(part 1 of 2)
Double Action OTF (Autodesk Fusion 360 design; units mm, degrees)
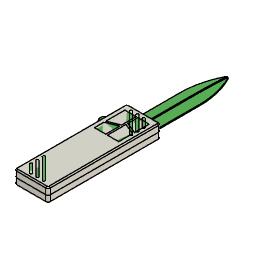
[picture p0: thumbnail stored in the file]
parameter "d3" = 3
parameter "d7" = 6
sketch "Sketch1" plane through (0, 0, 0) normal (0, 0, 1) x axis (1, 0, 0)
  line L1 (28, 2) -> (2, 2)
  line L2 (6, 96) -> (6, 100)
  line L3 (30, 0) -> (0, 0)
  line L4 (30, 100) -> (30, 0)
  line L5 (2, 98) -> (2, 2)
  line L6 (24, 96) -> (24, 100)
  line L7 (0, 100) -> (30, 100)
  line L8 (0, 0) -> (0, 100)
  line L9 (28, 98) -> (2, 98)
  line L10 (28, 2) -> (28, 98)
  line L11 (26, 4) -> (4, 4)
  line L12 (0.8, 36.7425) -> (0.8, 21)
  line L13 (24, 96) -> (26, 96)
  line L14 (4, 96) -> (6, 96)
  line L15 (5.1055, 19.9338) -> (0.9152, 44.9179)
  line L16 (4, 37.9285) -> (3, 37.9285)
  line L17 (4, 17.8) -> (0.8, 21)
  line L18 (4, 85) -> (0, 85)
  line L19 (4, 65) -> (0, 65)
  line L20 (29.2, 80) -> (26, 83.2)
  line L21 (29.2, 63.2575) -> (29.2, 80)
  line L22 (26, 62.0715) -> (26, 4)
  line L23 (26, 96) -> (26, 83.2)
  line L24 (26, 62.0715) -> (27, 62.0715)
  line L25 (28.014, 62.0715) -> (29.2, 63.2575)
  line L26 (24.8945, 80.0662) -> (29.0848, 55.0821)
  line L27 (24.1055, 79.9338) -> (28.1635, 55.7387)
  line L28 (4, 37.9285) -> (4, 96)
  line L29 (4, 4) -> (4, 17.8)
  line L30 (24, 96) -> (6, 96)
  line L31 (28.6, 44) -> (26, 44)
  line L32 (28.6, 4) -> (28.6, 44)
  line L33 (26, 4) -> (28.6, 4)
  line L34 (2.4, 54) -> (2.4, 65)
  line L35 (2.4, 96) -> (2.4, 85)
  line L36 (4, 96) -> (2.4, 96)
  line L37 (4, 54) -> (2.4, 54)
  line L38 (1.4, 4) -> (1.4, 20.4)
  line L39 (4, 4) -> (1.4, 4)
  line L40 (28.6, 96) -> (26, 96)
  line L41 (28.6, 80.6) -> (28.6, 96)
  line L42 (3, 37.9285) -> (1.9516, 44.1792)
  line L43 (1.986, 37.9285) -> (0.8, 45)
  line L44 (0.8, 36.7425) -> (1.986, 37.9285)
  line L45 (27, 62.0715) -> (28.0484, 55.8208)
  line L46 (28.014, 62.0715) -> (29.2, 55)
  line L47 (3.2, 44.3886) -> (1.9516, 44.1792)
  line L48 (3.0346, 45.3748) -> (3.2, 44.3886)
  line L49 (0.8, 45) -> (3.0346, 45.3748)
  line L50 (3.0848, 44.4706) -> (1.8365, 44.2613)
  line L51 (2.9525, 45.2596) -> (3.0848, 44.4706)
  line L52 (0.9152, 44.9179) -> (2.9525, 45.2596)
  line L53 (5.8945, 20.0662) -> (1.8365, 44.2613)
  line L54 (26.8, 55.6114) -> (28.0484, 55.8208)
  line L55 (26.9654, 54.6252) -> (26.8, 55.6114)
  line L56 (26.9654, 54.6252) -> (29.2, 55)
  line L57 (26.9152, 55.5294) -> (28.1635, 55.7387)
  line L58 (27.0475, 54.7404) -> (26.9152, 55.5294)
  line L59 (29.0848, 55.0821) -> (27.0475, 54.7404)
  line L60 (6, 4) -> (6, 96)
  line L61 (24, 4) -> (24, 96)
  line L62 (14, 4) -> (14, 96)
  line L63 (16, 4) -> (16, 96)
  circle C1 centre (2, 50) radius 1
  circle C2 centre (28, 98) radius 1
  circle C3 centre (2, 98) radius 1
  circle C4 centre (2, 2) radius 1
  circle C5 centre (28, 50) radius 1
  circle C6 centre (28, 2) radius 1
  arc A1 centre (5.5, 20) radius 0.4 clockwise from (5.8945, 20.0662) to (5.1055, 19.9338)
  arc A2 centre (24.5, 80) radius 0.4 clockwise from (24.1055, 79.9338) to (24.8945, 80.0662)
  point P6 (0, 0)
  point P15 (0, 0)
  point P14 (6, 100)
  point P12 (6, 96)
  point P3 (24, 100)
  point P17 (2, 98)
  point P21 (2, 98)
  point P10 (28, 2)
  point P23 (28, 2)
  point P11 (2, 2)
  point P22 (2, 2)
  point P9 (2, 50)
  point P24 (28, 50)
  point P25 (2, 98)
  point P13 (28, 98)
  point P20 (28, 98)
  point P1 (0, 0)
  point P29 (5.8523, 15.481)
  point P35 (4, 17.8)
  point P36 (0, 85)
  point P37 (4, 85)
  point P38 (0, 65)
  point P39 (4, 65)
  point P40 (26, 83.2)
  point P51 (26, 44)
  point P54 (2.4, 65)
  point P56 (2.4, 85)
  point P58 (4, 54)
  point P59 (1.4, 20.4)
  point P62 (28.6, 80.6)
  point P32 (5.8945, 20.0662)
  point P34 (5.8945, 20.0662)
  point P64 (1.986, 37.9285)
  point P42 (29.2, 63.2575)
  point P67 (29.2, 63.2575)
  point P45 (28.014, 62.0715)
  point P48 (24.8945, 80.0662)
  point P50 (24.8945, 80.0662)
  point P80 (6, 96)
  point P81 (6, 4)
  point P82 (24, 96)
  point P83 (24, 4)
  point P84 (14, 96)
  point P85 (14, 4)
  point P86 (16, 96)
  point P87 (16, 4)
  point P7 (30, 0)
  point P4 (0, 100)
  point P33 (5.5, 20)
  point P26 (0.8, 21)
  point P41 (29.2, 80)
  point P49 (24.5, 80)
  point P55 (2.4, 54)
  point P27 (4, 37.9285)
  point P28 (3, 37.9285)
  point P43 (26, 62.0715)
  point P44 (27, 62.0715)
  point P63 (0.8, 45)
  point P69 (3.2, 44.3886)
  point P66 (29.2, 55)
  point P75 (26.8, 55.6114)
  horizontal L3
  vertical L4
  horizontal L7
  vertical L8
  coincident P6 P15
  perpendicular L7 L28
  perpendicular L11 L28
  perpendicular L7 L22
  horizontal L13
  coincident P14 L7
  coincident P12 L13
  perpendicular L2 L13
  coincident P3 L7
  perpendicular L6 L13
  coincident P17 P21
  perpendicular L1 L4
  perpendicular L5 L7
  perpendicular L4 L9
  perpendicular L3 L10
  coincident P10 P23
  coincident P11 P22
  midpoint P9 L5
  midpoint P24 L10
  coincident P17 P25
  coincident P13 P20
  coincident P1 P6
  collinear L13 L14
  coincident P29 L15
  tangent L15 A1
  coincident P35 L28
  coincident L8 P36
  coincident P37 L28
  perpendicular L18 L28
  coincident L8 P38
  coincident P39 L28
  perpendicular L19 L28
  coincident P40 L22
  parallel L10 L21
  collinear L22 L23
  horizontal L24
  tangent L27 A2
  collinear L28 L29
  coincident L22 P51
  perpendicular L10 L31
  perpendicular L31 L32
  perpendicular L32 L33
  coincident L19 P54
  perpendicular L19 L34
  coincident L18 P56
  perpendicular L18 L35
  perpendicular L28 L36
  coincident L28 P58
  perpendicular L28 L37
  coincident L17 P59
  vertical L38
  perpendicular L38 L39
  perpendicular L23 L40
  coincident L20 P62
  perpendicular L40 L41
  coincident P32 P34
  horizontal L16
  coincident L16 P64
  coincident P42 P67
  coincident L24 P45
  coincident P48 P50
  tangent L26 A2
  parallel L15 L43
  perpendicular L42 L47
  perpendicular L43 L49
  perpendicular L50 L51
  parallel L49 L52
  parallel L48 L51
  parallel L47 L50
  parallel L15 L53
  tangent A1 L53
  parallel L27 L45
  perpendicular L45 L54
  perpendicular L54 L55
  perpendicular L27 L57
  perpendicular L57 L58
  perpendicular L46 L56
  parallel L56 L59
  coincident L30 P80
  coincident L11 P81
  perpendicular L11 L60
  coincident L30 P82
  coincident L11 P83
  perpendicular L11 L61
  coincident L30 P84
  coincident L11 P85
  perpendicular L11 L62
  coincident L30 P86
  coincident L11 P87
  perpendicular L11 L63
  dimension "d33" distance P6 P7 = 30
  dimension "d34" distance P4 P6 = 100
  dimension "d35" distance L4 L22 = 4
  dimension "d36" distance L3 L11 = 4
  dimension "d37" distance L7 L13 = 4
  dimension "d38" distance L2 L8 = 6
  dimension "d39" distance L4 L6 = 6 (= "d7")
  dimension "d40" distance L2 L6 = 18
  dimension "d41" distance L8 L28 = 4
  dimension "d42" diameter C2 = 2
  dimension "d43" diameter C1 = 2
  dimension "d44" diameter C5 = 2
  dimension "d45" diameter C4 = 2
  dimension "d46" diameter C6 = 2
  dimension "d47" distance L1 L3 = 2
  dimension "d48" distance L5 L8 = 2
  dimension "d49" diameter C3 = 2
  dimension "d50" distance L7 L9 = 2
  dimension "d51" distance L4 L10 = 2
  dimension "d64" distance L8 L12 = 0.8
  dimension "d87" distance L3 P33 = 20
  dimension "d89" angle L12 L17 = 135
  dimension "d90" distance L3 P26 = 21
  dimension "d95" distance L18 L19 = 20
  dimension "d96" distance L7 L18 = 15
  dimension "d100" angle L20 L21 = 135
  dimension "d101" distance L4 L21 = 0.8
  dimension "d102" distance L7 P41 = 20
  dimension "d105" angle L21 L25 = 135
  dimension "d115" distance L26 L27 = 0.8
  dimension "d118" distance L7 P49 = 20
  dimension "d204" distance L22 L32 = 2.6
  dimension "d205" distance L4 L32 = 1.4
  dimension "d206" distance L31 L33 = 40
  dimension "d225" distance P54 P55 = 11
  dimension "d226" distance L28 L35 = 1.6
  dimension "d227" distance L28 L34 = 1.6
  dimension "d282" distance L29 L38 = 2.6
  dimension "d283" distance L23 L41 = 2.6
  dimension "d311" distance L8 P33 = 5.5
  dimension "d328" distance L15 P64 = 0.1
  dimension "d329" distance P27 P28 = 1
  dimension "d330" angle L12 L44 = 135
  dimension "d331" distance P43 P44 = 1
  dimension "d335" distance P44 L27 = 0.1
  dimension "d338" distance L8 P63 = 0.8
  dimension "d340" distance L3 P63 = 45
  dimension "d341" distance L28 P69 = 0.8
  dimension "d343" distance L49 L52 = 0.1
  dimension "d344" distance L48 L51 = 0.1
  dimension "d345" distance L47 L50 = 0.1
  dimension "d346" distance L50 L52 = 0.8
  dimension "d347" distance L42 L53 = 0.1
  dimension "d348" distance L15 L53 = 0.8
  dimension "d350" distance L4 P66 = 0.8
  dimension "d351" distance L7 P66 = 45
  dimension "d352" distance L22 P75 = 0.8
  dimension "d353" distance L56 L59 = 0.1
  dimension "d354" distance L55 L58 = 0.1
  dimension "d355" distance L54 L57 = 0.1
  dimension "d356" distance L57 L59 = 0.8
  dimension "d362" distance L28 L60 = 2
  dimension "d363" distance L22 L61 = 2
  dimension "d364" distance L61 L63 = 8
  dimension "d365" distance L60 L62 = 8
  dimension "d366" distance L62 L63 = 2
  dimension "d376" distance L4 P49 = 5.5
sketch "Sketch1" plane through (0, 0, 0) normal (0, 0, 1) x axis (1, 0, 0)
  line L1 (26, 4) -> (4, 4)
  line L2 (6, 96) -> (6, 100)
  line L3 (0, 100) -> (30, 100)
  line L4 (24, 96) -> (24, 100)
  line L5 (25.85, 4.15) -> (6.15, 4.15)
  line L6 (12.15, 6.65) -> (12.15, 16.65)
  line L7 (17.85, 6.65) -> (17.85, 16.65)
  line L8 (15, 99.15) -> (15, 4.15)
  line L9 (6, 19.15) -> (6, 96)
  line L10 (24, 19.15) -> (24, 96)
  line L11 (6.15, 64.15) -> (6.15, 19.15)
  line L12 (23.85, 64.15) -> (23.85, 19.15)
  line L13 (24, 96) -> (26, 96)
  line L14 (16.85, 5.65) -> (13.15, 5.65)
  line L15 (16.85, 17.65) -> (13.15, 17.65)
  line L16 (26, 62.0715) -> (26, 4)
  line L17 (23.85, 19.15) -> (24.85, 19.15)
  line L18 (4.15, 19.15) -> (6.15, 19.15)
  line L19 (4, 37.9285) -> (4, 96)
  line L20 (4, 4) -> (4, 17.8)
  line L21 (23.85, 19.15) -> (6.15, 19.15)
  line L22 (16.85, 4.65) -> (13.15, 4.65)
  line L23 (16.85, 18.65) -> (13.15, 18.65)
  line L24 (17.85, 4.9179) -> (17.85, 6.65)
  line L25 (12.15, 4.9179) -> (12.15, 6.65)
  line L26 (12.15, 18.3821) -> (12.15, 16.65)
  line L27 (17.85, 18.3821) -> (17.85, 16.65)
  line L28 (5.8821, 14.15) -> (4.4179, 16.6859)
  line L29 (4.15, 17.6859) -> (4.15, 19.15)
  line L30 (25.5821, 6.6141) -> (24.1179, 9.15)
  line L31 (25.85, 5.6141) -> (25.85, 4.15)
  line L32 (6.15, 4.15) -> (6.15, 13.15)
  line L33 (23.85, 10.901) -> (23.85, 10.15)
  line L34 (24.85, 19.15) -> (23.8809, 11.3971)
  arc A1 centre (79.784, 64.15) radius 73.634 clockwise from (6.15, 64.15) to (15, 99.15)
  arc A2 centre (-49.784, 64.15) radius 73.634 clockwise from (15, 99.15) to (23.85, 64.15)
  arc A3 centre (13.15, 16.65) radius 1 clockwise from (12.15, 16.65) to (13.15, 17.65)
  arc A4 centre (16.85, 16.65) radius 1 clockwise from (16.85, 17.65) to (17.85, 16.65)
  arc A5 centre (16.85, 6.65) radius 1 clockwise from (17.85, 6.65) to (16.85, 5.65)
  arc A6 centre (13.15, 6.65) radius 1 clockwise from (13.15, 5.65) to (12.15, 6.65)
  arc A7 centre (13.15, 6.65) radius 2 clockwise from (13.15, 4.65) to (12.15, 4.9179)
  arc A8 centre (16.85, 6.65) radius 2 clockwise from (17.85, 4.9179) to (16.85, 4.65)
  arc A9 centre (16.85, 16.65) radius 2 clockwise from (16.85, 18.65) to (17.85, 18.3821)
  arc A10 centre (13.15, 16.65) radius 2 clockwise from (12.15, 18.3821) to (13.15, 18.65)
  arc A11 centre (6.15, 17.6859) radius 2 clockwise from (4.4179, 16.6859) to (4.15, 17.6859)
  arc A12 centre (4.15, 13.15) radius 2 clockwise from (5.8821, 14.15) to (6.15, 13.15)
  arc A13 centre (25.85, 10.15) radius 2 clockwise from (24.1179, 9.15) to (23.85, 10.15)
  arc A14 centre (23.85, 5.6141) radius 2 clockwise from (25.5821, 6.6141) to (25.85, 5.6141)
  arc A15 centre (27.85, 10.901) radius 4 clockwise from (23.85, 10.901) to (23.8809, 11.3971)
  point P6 (6, 96)
  point P15 (6, 96)
  point P16 (6, 19.15)
  point P10 (24, 96)
  point P17 (24, 96)
  point P18 (24, 19.15)
  point P19 (6.15, 19.15)
  point P54 (4.15, 6.15)
  point P53 (4.15, 17.15)
  point P61 (25.85, 17.15)
  point P62 (25.85, 6.15)
  point P13 (15, 4.15)
  point P71 (23.85, 11.15)
  point P20 (6.15, 64.15)
  point P14 (15, 99.15)
  point P12 (4.15, 19.15)
  point P11 (25.85, 4.15)
  point P70 (24.85, 19.15)
  point P63 (23.85, 10.15)
  horizontal L5
  vertical L31
  horizontal L17
  vertical L29
  perpendicular L5 L6
  perpendicular L1 L7
  perpendicular L3 L8
  coincident P6 P15
  coincident P16 L17
  perpendicular L9 L17
  coincident P10 P17
  coincident P18 L17
  perpendicular L10 L17
  coincident P19 L17
  perpendicular L11 L17
  perpendicular L12 L17
  equal L11 L12
  tangent L11 A1
  tangent L12 A2
  perpendicular L7 L14
  perpendicular L7 L15
  tangent L15 A3
  tangent L6 A3
  tangent L15 A4
  tangent L7 A4
  equal A3 A4
  tangent L14 A5
  tangent L7 A5
  equal A3 A5
  tangent L14 A6
  tangent L6 A6
  equal A3 A6
  collinear L17 L18
  tangent A5 L24
  tangent A6 L25
  concentric A6 A7
  concentric A5 A8
  tangent A7 L22
  tangent L22 A8
  tangent A3 L26
  tangent A4 L27
  concentric A4 A9
  concentric A3 A10
  tangent A9 L23
  tangent L23 A10
  coincident P54 L29
  coincident P53 L28
  coincident P53 L29
  tangent L28 A11
  tangent L29 A11
  tangent L28 A12
  equal A11 A12
  coincident P61 L31
  tangent L30 A13
  coincident P62 L30
  coincident P62 L31
  tangent L30 A14
  tangent L31 A14
  tangent A12 L32
  coincident L5 P13
  vertical L33
  tangent A13 L33
  coincident P71 L33
  coincident P71 L34
  tangent L33 A15
  tangent L34 A15
  collinear L12 L33
  dimension "d54" distance L1 L5 = 0.15
  dimension "d56" distance L6 L7 = 5.7
  dimension "d57" distance L6 L29 = 8
  dimension "d58" distance L7 L31 = 8
  dimension "d59" distance P19 P20 = 45
  dimension "d60" distance L9 L11 = 0.15
  dimension "d61" distance L10 L12 = 0.15
  dimension "d91" distance L14 L15 = 12
  dimension "d92" distance L5 L14 = 1.5
  dimension "d93" distance L15 L17 = 1.5
  dimension "d94" radius A3 = 1
  dimension "d119" distance L16 L31 = 0.15
  dimension "d129" distance P13 P14 = 95
  dimension "d139" distance L20 L29 = 0.15
  dimension "d313" distance P12 P53 = 2
  dimension "d316" angle L28 L29 = 30
  dimension "d318" radius A11 = 2
  dimension "d319" distance P11 P62 = 2
  dimension "d322" angle L30 L31 = 30
  dimension "d370" distance L29 L32 = 2
  dimension "d371" distance L5 L21 = 15
  dimension "d372" distance L12 P70 = 1
  dimension "d373" distance P63 P71 = 1
  dimension "d374" radius A15 = 4
  dimension "d375" radius A13 = 2
sketch "Sketch1" plane through (0, 0, 0) normal (0, 0, 1) x axis (1, 0, 0)
  line L1 (4, 85) -> (0, 85)
  line L2 (4, 96) -> (6, 96)
  line L3 (24, 96) -> (26, 96)
  line L4 (26, 96) -> (26, 83.2)
  line L5 (26, 62.0715) -> (26, 4)
  line L6 (4, 65) -> (0, 65)
  line L7 (0, 0) -> (0, 100)
  line L8 (26, 4) -> (4, 4)
  line L9 (4.2, 75.2) -> (0.1142, 75.2)
  line L10 (-0.3, 65.2) -> (-0.3, 75.2)
  line L11 (4.2, 65.2) -> (0.1142, 65.2)
  line L12 (4.2, 86.2) -> (4.2, 75.2)
  line L13 (25.8, 86.2) -> (4.2, 86.2)
  line L14 (-5.3, 70.2) -> (-0.3, 70.2)
  line L15 (-2.4716, 67.3716) -> (-0.5929, 65.4929)
  line L16 (-2.4716, 73.0284) -> (-0.5929, 74.9071)
  line L17 (7.2, 29.2665) -> (7.2, 17.2665)
  line L18 (4.2, 37.5089) -> (4.2, 65.2)
  line L19 (4, 37.9285) -> (4, 96)
  line L20 (4, 4) -> (4, 17.8)
  line L21 (12.15, 6.65) -> (12.15, 16.65)
  line L22 (17.85, 6.65) -> (17.85, 16.65)
  line L23 (10.8, 5.65) -> (12, 5.65)
  line L24 (10.8, 84.7) -> (10.8, 5.65)
  line L25 (12, 84.7) -> (10.8, 84.7)
  line L26 (12, 5.65) -> (12, 84.7)
  line L27 (25.85, 4.15) -> (6.15, 4.15)
  line L28 (18, 84.7) -> (18, 5.65)
  line L29 (19.2, 84.7) -> (18, 84.7)
  line L30 (19.2, 5.65) -> (19.2, 84.7)
  line L31 (18, 5.65) -> (19.2, 5.65)
  line L32 (22.85, 61.1908) -> (22.85, 73.1908)
  line L33 (25.85, 34.2) -> (25.85, 52.9483)
  line L34 (21.65, 60.9792) -> (21.65, 73.4568)
  line L35 (8.4, 29.4781) -> (8.4, 17.0004)
  line L36 (5.4, 86.2) -> (5.4, 65.2)
  line L37 (4.2, 75.2) -> (4.2, 65.2)
  line L38 (26, 4) -> (28.6, 4)
  line L39 (28.6, 4) -> (28.6, 44)
  line L40 (28.6, 44) -> (26, 44)
  line L41 (26.45, 4.15) -> (25.85, 4.15)
  line L42 (28.45, 32.2) -> (28.45, 6.15)
  line L43 (25.85, 34.2) -> (26.45, 34.2)
  line L44 (2.6, 86.2) -> (2.6, 75.2)
  line L45 (4.2, 86.2) -> (2.6, 86.2)
  line L46 (2.6, 54.4) -> (2.6, 65.2)
  line L47 (4.2, 54.4) -> (2.6, 54.4)
  line L48 (1.4, 4) -> (1.4, 20.4)
  line L49 (4, 4) -> (1.4, 4)
  line L50 (28.6, 96) -> (26, 96)
  line L51 (28.6, 80.6) -> (28.6, 96)
  line L52 (28.45, 86.2) -> (25.8, 86.2)
  line L53 (28.45, 85.2) -> (28.45, 86.2)
  line L54 (22.85, 73.1908) -> (28.45, 85.2)
  line L55 (27.5923, 86.2) -> (21.65, 73.4568)
  line L56 (1.55, 4.15) -> (6.15, 4.15)
  line L57 (1.55, 5.15) -> (1.55, 4.15)
  line L58 (1.55, 5.15) -> (7.2, 17.2665)
  line L59 (2.4077, 4.15) -> (8.4, 17.0004)
  line L60 (9.8, 5.65) -> (10.8, 5.65)
  line L61 (9.8, 84.7) -> (9.8, 5.65)
  line L62 (10.8, 84.7) -> (9.8, 84.7)
  line L63 (20.2, 5.65) -> (19.2, 5.65)
  line L64 (20.2, 84.7) -> (20.2, 5.65)
  line L65 (19.2, 84.7) -> (20.2, 84.7)
  line L66 (24.8, 4.15) -> (24.8, 52.3246)
  line L67 (5.4, 37.7205) -> (8.4, 29.4781)
  line L68 (4.2, 37.5089) -> (7.2, 29.2665)
  line L69 (5.4, 37.7205) -> (5.4, 65.2)
  line L70 (24.8, 52.3246) -> (21.65, 60.9792)
  line L71 (25.85, 52.9483) -> (22.85, 61.1908)
  arc A1 centre (0.3569, 70.2) radius 4 clockwise from (-2.4716, 67.3716) to (-2.4716, 73.0284)
  arc A2 centre (0.1142, 66.2) radius 1 clockwise from (0.1142, 65.2) to (-0.5929, 65.4929)
  arc A3 centre (0.1142, 74.2) radius 1 clockwise from (-0.5929, 74.9071) to (0.1142, 75.2)
  arc A4 centre (26.45, 32.2) radius 2 clockwise from (26.45, 34.2) to (28.45, 32.2)
  arc A5 centre (26.45, 6.15) radius 2 clockwise from (28.45, 6.15) to (26.45, 4.15)
  point P22 (-0.3, 70.2)
  point P23 (-5.3, 70.2)
  point P52 (5.4, 86.2)
  point P18 (-0.3, 65.2)
  point P16 (-0.3, 75.2)
  point P40 (25.85, 4.15)
  point P62 (25.85, 4.15)
  point P70 (2.6, 75.2)
  point P72 (2.6, 65.2)
  point P74 (4.2, 54.4)
  point P81 (27.5923, 86.2)
  point P39 (6.15, 4.15)
  point P82 (6.15, 4.15)
  point P85 (2.4077, 4.15)
  point P90 (24.8, 4.15)
  point P27 (7.2, 17.2665)
  point P28 (7.2, 29.2665)
  point P45 (22.85, 73.1908)
  point P46 (22.85, 61.1908)
  point P73 (2.6, 54.4)
  point P79 (28.45, 86.2)
  point P80 (28.45, 85.2)
  point P83 (1.55, 4.15)
  point P84 (1.55, 5.15)
  perpendicular L7 L9
  perpendicular L9 L10
  perpendicular L11 L18
  perpendicular L9 L12
  perpendicular L12 L13
  collinear L12 L18
  midpoint L10 P22
  perpendicular L10 L14
  coincident P23 L16
  coincident P23 L15
  tangent L16 A1
  tangent L15 A1
  vertical L17
  perpendicular L24 L25
  vertical L26
  vertical L24
  parallel L22 L28
  perpendicular L28 L29
  perpendicular L27 L30
  perpendicular L28 L31
  coincident L13 P52
  perpendicular L13 L36
  coincident P18 L11
  coincident P18 L15
  tangent L11 A2
  tangent L15 A2
  coincident P16 L9
  coincident P16 L16
  tangent L9 A3
  tangent L16 A3
  equal A2 A3
  coincident P40 P62
  perpendicular L5 L41
  perpendicular L33 L43
  vertical L42
  tangent L42 A4
  tangent L43 A4
  tangent L41 A5
  tangent L42 A5
  coincident L9 P70
  perpendicular L1 L44
  perpendicular L44 L45
  coincident L11 P72
  perpendicular L6 L46
  coincident L18 P74
  perpendicular L18 L47
  perpendicular L4 L52
  perpendicular L52 L53
  coincident L52 P81
  parallel L54 L55
  coincident P39 P82
  perpendicular L27 L57
  coincident L56 P85
  parallel L58 L59
  horizontal L56
  perpendicular L24 L60
  perpendicular L23 L61
  perpendicular L30 L63
  perpendicular L63 L64
  perpendicular L24 L62
  perpendicular L30 L65
  coincident L27 P90
  perpendicular L27 L66
  parallel L70 L71
  dimension "d120" distance P16 P18 = 10
  dimension "d122" distance L6 L11 = 0.2
  dimension "d124" distance L7 L10 = 0.3
  dimension "d125" distance P22 P23 = 5
  dimension "d126" radius A1 = 4
  dimension "d128" distance L9 L13 = 11
  dimension "d136" distance P27 L18 = 3
  dimension "d137" distance P27 P28 = 12
  dimension "d141" distance L24 L26 = 1.2
  dimension "d142" distance L21 L26 = 0.15
  dimension "d143" distance L23 L27 = 1.5
  dimension "d144" distance L13 L25 = 1.5
  dimension "d145" distance L28 L30 = 1.2
  dimension "d146" distance L22 L28 = 0.15
  dimension "d147" distance L27 L31 = 1.5
  dimension "d148" distance L13 L29 = 1.5
  dimension "d151" distance P45 P46 = 12
  dimension "d176" radius A2 = 1
  dimension "d207" distance L39 L42 = 0.15
  dimension "d208" distance L40 L43 = 9.8
  dimension "d209" radius A4 = 2
  dimension "d210" radius A5 = 2
  dimension "d228" distance L12 L44 = 1.6
  dimension "d229" distance P72 P73 = 10.8
  dimension "d230" distance L18 L46 = 1.6
  dimension "d285" distance P79 P80 = 1
  dimension "d286" distance L51 L53 = 0.15
  dimension "d287" distance L54 L55 = 1.2
  dimension "d288" distance L32 L33 = 3
  dimension "d289" distance L5 L33 = 0.15
  dimension "d290" angle L53 L54 = 155
  dimension "d291" distance P83 P84 = 1
  dimension "d292" distance L48 L57 = 0.15
  dimension "d293" distance L58 L59 = 1.2
  dimension "d294" angle L57 L58 = 155
  dimension "d295" distance L18 L19 = 0.2
  dimension "d296" distance L24 L61 = 1
  dimension "d297" distance L30 L64 = 1
  dimension "d336" distance L8 L27 = 0.15
  dimension "d337" distance L5 L66 = 1.2
  dimension "d358" angle L17 L68 = 160
  dimension "d359" distance L67 L68 = 1.2
  dimension "d360" angle L32 L71 = 160
  dimension "d361" distance L70 L71 = 1.2
extrude "Extrude1" new body sketch "Sketch1" profile of L29 C1 L2 L14 C2 C3 C4 L6 L7 C5 L8 L23 C6 L11 L12 L16 L53 L15 A1 L17 L18 L19 L20 L21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 along normal blind 2
extrude "Extrude5" cut sketch "Sketch1" profile of L11 L27 A2 L30 L60 L61 L62 L63 blind -0.4 from offset 2
extrude "Extrude4" add sketch "Sketch1" profile of L29 L23 L17 L20 L31 L32 L33 L38 L39 L40 L41 along normal blind 4.2
extrude "Extrude2" add sketch "Sketch1" profile of L29 C1 L2 L14 C2 L3 C3 L4 C4 L6 L7 C5 L8 L23 C6 L11 L12 L16 L17 L18 L19 L20 L21 L24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 along normal blind 6.2
extrude "Extrude3" new body sketch "Sketch1" profile of L53 L15 A1 L26 L27 A2 L50 L51 L52 L57 L58 L59 blind 8 from offset 2.2
extrude "Extrude1" new body sketch "Sketch1" profile of L5 L31 L18 L29 L6 L7 L14 L15 A3 A4 A5 A6 L21 blind 2 from offset 2.2
extrude "Extrude3" add sketch "Sketch1" profile of L11 L12 A1 A2 L21 blind 1 from offset 2.2
extrude "Extrude2" add sketch "Sketch1" profile of L6 L7 L14 L15 A3 A4 A5 A6 blind 5.8 from offset 2.2
extrude "Extrude4" add sketch "Sketch1" profile of L14 L15 A3 A4 A5 A6 L22 A7 A8 A9 L23 A10 L24 L25 L26 L27 blind 1 from offset 7
work_plane "WorkPlane1"
sketch "Sketch2" plane through (15, 0, 0) normal (1, 0, 0) x axis (0, 1, 0)
  line L1 (19.15, 3.2) -> (64.15, 3.2)
  line L2 (64.15, 3.2) -> (99.15, 3.2)
  line L3 (19.15, 4.2) -> (19.15, 2.2)
  line L4 (64.15, 4.2) -> (19.15, 4.2)
  line L5 (19.15, 4.2) -> (19.15, 3.2)
  line L6 (99.15, 3.2) -> (19.15, 3.2)
  arc A1 centre (64.15, -608.8) radius 613 clockwise from (64.15, 4.2) to (99.15, 3.2)
  point P6 (19.15, 4.2)
  point P7 (19.15, 4.2)
  point P4 (99.15, 3.2)
  point P9 (99.15, 3.2)
  point P2 (64.15, 3.2)
  point P8 (64.15, 4.2)
  point P3 (19.15, 3.2)
  point P11 (19.15, 3.2)
  point P12 (19.15, 4.2)
  coincident P6 P7
  perpendicular L3 L4
  coincident P4 P9
  tangent L4 A1
  vertical P2 P8
  coincident P3 P11
  coincident P6 P12
loft "Loft1" sketch "Sketch2"
loft "Loft2"
fillet "Fillet1" radius 1 5
extrude "Extrude1" new body sketch "Sketch1" profile of L5 L9 L11 L18 L12 L13 L33 L17 L19 L20 L23 L24 L25 L26 L27 L28 L29 L30 L31 L32 L34 L69 L35 L36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 blind 5.8 from offset 4.4
extrude "Extrude6" add sketch "Sketch1" profile of L24 L30 L60 L61 L62 L63 L64 L65 blind 1 from offset 4.4
extrude "Extrude2" add sketch "Sketch1" profile of L5 L13 L33 L20 L23 L24 L25 L26 L27 L28 L29 L30 L31 L32 L34 L69 L35 L36 L41 L42 L43 A4 A5 L52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 blind 2 from offset 8.2
extrude "Extrude5" add sketch "Sketch1" profile of L1 L6 L7 L9 L11 L15 L16 A1 L19 A2 A3 L44 L45 L46 L47 blind 8 from offset 2.2
extrude "Extrude1" new body sketch "Sketch1" profile of L29 C1 L2 L14 C2 L3 C3 L4 C4 L6 L7 C5 L8 L23 C6 L11 L12 L16 L17 L18 L19 L20 L21 L24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 blind 6.2 from offset 6.2
extrude "Extrude5" add sketch "Sketch1" profile of L29 L14 L8 L23 L11 L12 L16 L53 L15 A1 L17 L18 L19 L20 L21 L24 L25 L26 L27 A2 L30 L31 L32 L33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 blind 2 from offset 10.4
extrude "Extrude3" add sketch "Sketch1" profile of C1 C2 C3 C4 C5 C6 blind 2 from offset 10.4
extrude "Extrude4" add sketch "Sketch1" profile of L2 L6 L7 L30 blind 8 from offset 4.4
position "Position1"
fillet "Fillet2" radius 2
chamfer "Chamfer2" distance 1 distance 0.5
sketch "Sketch1" plane through (0, 100, 0) normal (0, 1, 0) x axis (-1, 0, 0)
  line L1 (-6, 2) -> (-6, 6.2)
  line L2 (-24, 6.2) -> (-24, 2)
  line L3 (-28, 6.2) -> (-24, 6.2)
  line L4 (-28, 1) -> (-28, 6.2)
  line L5 (-2, 1) -> (-28, 1)
  line L6 (-2, 6.2) -> (-2, 1)
  line L7 (-6, 6.2) -> (-2, 6.2)
  line L8 (-24, 2) -> (-6, 2)
  line L9 (-6, 4.4) -> (-24, 4.4)
  line L10 (-5.5, 4.9) -> (-24.5, 4.9)
  line L11 (-5.5, 1.5) -> (-5.5, 4.9)
  line L12 (-24.5, 1.5) -> (-5.5, 1.5)
  line L13 (-24.5, 4.9) -> (-24.5, 1.5)
  line L14 (-2, 1) -> (-28, 1)
  line L15 (-2, 6.2) -> (-2, 1)
  line L16 (-6, 6.2) -> (-2, 6.2)
  line L17 (-28, 1) -> (-28, 6.2)
  line L18 (-6, 2) -> (-6, 6.2)
  line L19 (-24, 2) -> (-6, 2)
  line L20 (-24, 6.2) -> (-24, 2)
  line L21 (-28, 6.2) -> (-24, 6.2)
  horizontal L10
  vertical L11
  horizontal L12
  vertical L13
  dimension "d234" distance L1 L11 = 0.5
  dimension "d235" distance L8 L12 = 0.5
  dimension "d236" distance L2 L13 = 0.5
  dimension "d237" distance L9 L10 = 0.5
extrude "Extrude1" new body sketch "Sketch1" profile of L1 L2 L8 L9 L10 L11 L12 L13 against normal blind 0.5
chamfer "Chamfer1" distance 0.5
combine "Combine1"
sketch "Sketch1" plane through (0, 0, 12.4) normal (0, 0, 1) x axis (-1, 0, 0)
  line L1 (-28, -1) -> (-2, -1)
  line L2 (-1, -98) -> (-1, -2)
  line L3 (-2, -1) -> (-28, -1)
  line L4 (-26.7071, -89.7071) -> (-19.7071, -96.7071)
  line L5 (-25.2929, -88.2929) -> (-18.2929, -95.2929)
  line L6 (-26.7071, -84.0503) -> (-14.0503, -96.7071)
  line L7 (-25.2929, -82.636) -> (-12.636, -95.2929)
  line L8 (-26.7071, -78.3934) -> (-8.3934, -96.7071)
  line L9 (-25.2929, -76.9792) -> (-6.9792, -95.2929)
  line L10 (-10.2929, -3.2929) -> (-3.2929, -10.2929)
  line L11 (-11.7071, -4.7071) -> (-4.7071, -11.7071)
  line L12 (-15.9497, -3.2929) -> (-3.2929, -15.9497)
  line L13 (-17.364, -4.7071) -> (-4.7071, -17.364)
  line L14 (-21.6066, -3.2929) -> (-3.2929, -21.6066)
  line L15 (-23.0208, -4.7071) -> (-4.7071, -23.0208)
  line L16 (-2, -99) -> (-28, -99)
  line L17 (-1, -2) -> (-1, -98)
  line L18 (-29, -98) -> (-29, -2)
  line L19 (-28, -99) -> (-2, -99)
  line L20 (-29, -2) -> (-29, -98)
  arc A1 centre (-28, -98) radius 1 clockwise from (-28, -99) to (-29, -98)
  arc A2 centre (-2, -98) radius 1 clockwise from (-1, -98) to (-2, -99)
  arc A3 centre (-2, -2) radius 1 clockwise from (-2, -1) to (-1, -2)
  arc A4 centre (-28, -2) radius 1 clockwise from (-29, -2) to (-28, -1)
  arc A5 centre (-19, -96) radius 1 clockwise from (-18.2929, -95.2929) to (-19.7071, -96.7071)
  arc A6 centre (-26, -89) radius 1 clockwise from (-26.7071, -89.7071) to (-25.2929, -88.2929)
  arc A7 centre (-13.3431, -96) radius 1 clockwise from (-12.636, -95.2929) to (-14.0503, -96.7071)
  arc A8 centre (-7.6863, -96) radius 1 clockwise from (-6.9792, -95.2929) to (-8.3934, -96.7071)
  arc A9 centre (-26, -83.3431) radius 1 clockwise from (-26.7071, -84.0503) to (-25.2929, -82.636)
  arc A10 centre (-26, -77.6863) radius 1 clockwise from (-26.7071, -78.3934) to (-25.2929, -76.9792)
  arc A11 centre (-4, -11) radius 1 clockwise from (-3.2929, -10.2929) to (-4.7071, -11.7071)
  arc A12 centre (-4, -16.6569) radius 1 clockwise from (-3.2929, -15.9497) to (-4.7071, -17.364)
  arc A13 centre (-4, -22.3137) radius 1 clockwise from (-3.2929, -21.6066) to (-4.7071, -23.0208)
  arc A14 centre (-22.3137, -4) radius 1 clockwise from (-23.0208, -4.7071) to (-21.6066, -3.2929)
  arc A15 centre (-16.6569, -4) radius 1 clockwise from (-17.364, -4.7071) to (-15.9497, -3.2929)
  arc A16 centre (-11, -4) radius 1 clockwise from (-11.7071, -4.7071) to (-10.2929, -3.2929)
  arc A17 centre (-28, -98) radius 1 clockwise from (-28, -99) to (-29, -98)
  arc A18 centre (-2, -98) radius 1 clockwise from (-1, -98) to (-2, -99)
  arc A19 centre (-2, -2) radius 1 clockwise from (-2, -1) to (-1, -2)
  arc A20 centre (-28, -2) radius 1 clockwise from (-29, -2) to (-28, -1)
  point P51 (-11, -4)
  point P47 (-4, -16.6569)
  point P48 (-4, -22.3137)
  point P50 (-16.6569, -4)
  point P49 (-22.3137, -4)
  parallel L4 L5
  tangent L4 A5
  tangent L5 A5
  tangent L5 A6
  tangent L4 A6
  parallel L5 L6
  parallel L6 L7
  parallel L7 L8
  parallel L8 L9
  tangent L6 A7
  tangent L8 A8
  tangent L9 A10
  tangent L8 A10
  tangent L7 A9
  tangent L6 A9
  tangent L7 A7
  tangent L9 A8
  parallel L10 L11
  parallel L11 L12
  parallel L12 L13
  parallel L13 L14
  parallel L14 L15
  tangent L13 A12
  tangent L15 A13
  tangent L15 A14
  tangent L13 A15
  tangent L10 A16
  tangent L11 A16
  tangent L12 A15
  tangent L14 A14
  tangent L14 A13
  tangent L12 A12
  tangent L10 A11
  tangent L11 A11
  dimension "d249" distance L4 L5 = 2
  dimension "d253" distance L6 L7 = 2
  dimension "d254" distance L5 L6 = 2
  dimension "d255" distance L7 L8 = 2
  dimension "d256" distance L8 L9 = 2
  dimension "d262" angle L3 L10 = 45
  dimension "d263" distance L10 L11 = 2
  dimension "d264" distance L12 L13 = 2
  dimension "d265" distance L14 L15 = 2
  dimension "d266" distance L13 L14 = 2
  dimension "d267" distance L11 L12 = 2
  dimension "d268" distance L3 P51 = 3
  dimension "d270" distance L2 P47 = 3
  dimension "d271" distance L2 P48 = 3
  dimension "d272" distance L3 P50 = 3
  dimension "d273" distance L1 P49 = 3
  dimension "d274" distance L2 P51 = 10
extrude "Extrude1" new body sketch "Sketch1" profile of L4 L5 A5 A6 L6 L7 L8 L9 A7 A8 A9 A10 L10 L11 L12 L13 L14 L15 A11 A12 A13 A14 A15 A16 against normal blind 1
combine "Combine1"
extrude "Extrude2" new body of existing geometry blind 1 from offset -12.4
combine "Combine2"
work_plane "WorkPlane1" AlongDistance -15
extrude "Extrude5" cut sketch "Sketch1" profile of L5 L31 L18 L29 L6 L7 L21 L22 A7 A8 A9 L23 A10 L24 L25 L26 L27 blind 1 from offset 4.2
chamfer "Chamfer3" distance 0.4 distance 3
sketch "Sketch1" plane through (0, 0, 0) normal (0, 0, 1) x axis (1, 0, 0)
  line L1 (26, 4) -> (4, 4)
  line L2 (6, 96) -> (6, 100)
  line L3 (0, 100) -> (30, 100)
  line L4 (24, 96) -> (24, 100)
  line L5 (25.85, 4.15) -> (6.15, 4.15)
  line L6 (12.15, 6.65) -> (12.15, 16.65)
  line L7 (17.85, 6.65) -> (17.85, 16.65)
  line L8 (6, 19.15) -> (6, 96)
  line L9 (24, 19.15) -> (24, 96)
  line L10 (23.85, 99.15) -> (23.85, 19.15)
  line L11 (24, 96) -> (26, 96)
  line L12 (16.85, 5.65) -> (13.15, 5.65)
  line L13 (16.85, 17.65) -> (13.15, 17.65)
  line L14 (26, 62.0715) -> (26, 4)
  line L15 (23.85, 19.15) -> (24.85, 19.15)
  line L16 (4.15, 19.15) -> (6.15, 19.15)
  line L17 (4, 37.9285) -> (4, 96)
  line L18 (4, 4) -> (4, 17.8)
  line L19 (23.85, 19.15) -> (6.15, 19.15)
  line L20 (16.85, 4.65) -> (13.15, 4.65)
  line L21 (16.85, 18.65) -> (13.15, 18.65)
  line L22 (17.85, 4.9179) -> (17.85, 6.65)
  line L23 (12.15, 4.9179) -> (12.15, 6.65)
  line L24 (12.15, 18.3821) -> (12.15, 16.65)
  line L25 (17.85, 18.3821) -> (17.85, 16.65)
  line L26 (5.8821, 14.15) -> (4.4179, 16.6859)
  line L27 (4.15, 17.6859) -> (4.15, 19.15)
  line L28 (25.5821, 6.6141) -> (24.1179, 9.15)
  line L29 (25.85, 5.6141) -> (25.85, 4.15)
  line L30 (6.15, 4.15) -> (6.15, 13.15)
  line L31 (23.85, 10.901) -> (23.85, 10.15)
  line L32 (24.85, 19.15) -> (23.8809, 11.3971)
  line L33 (23.85, 99.15) -> (6.15, 99.15)
  line L34 (18.35, 24.15) -> (6.65, 24.15)
  line L35 (18.85, 24.6826) -> (18.85, 24.65)
  line L36 (6.65, 25.1826) -> (18.35, 25.1826)
  line L37 (6.15, 26.1826) -> (6.15, 25.6826)
  line L38 (6.15, 99.15) -> (6.15, 19.15)
  arc A1 centre (13.15, 16.65) radius 1 clockwise from (12.15, 16.65) to (13.15, 17.65)
  arc A2 centre (16.85, 16.65) radius 1 clockwise from (16.85, 17.65) to (17.85, 16.65)
  arc A3 centre (16.85, 6.65) radius 1 clockwise from (17.85, 6.65) to (16.85, 5.65)
  arc A4 centre (13.15, 6.65) radius 1 clockwise from (13.15, 5.65) to (12.15, 6.65)
  arc A5 centre (13.15, 6.65) radius 2 clockwise from (13.15, 4.65) to (12.15, 4.9179)
  arc A6 centre (16.85, 6.65) radius 2 clockwise from (17.85, 4.9179) to (16.85, 4.65)
  arc A7 centre (16.85, 16.65) radius 2 clockwise from (16.85, 18.65) to (17.85, 18.3821)
  arc A8 centre (13.15, 16.65) radius 2 clockwise from (12.15, 18.3821) to (13.15, 18.65)
  arc A9 centre (6.15, 17.6859) radius 2 clockwise from (4.4179, 16.6859) to (4.15, 17.6859)
  arc A10 centre (4.15, 13.15) radius 2 clockwise from (5.8821, 14.15) to (6.15, 13.15)
  arc A11 centre (25.85, 10.15) radius 2 clockwise from (24.1179, 9.15) to (23.85, 10.15)
  arc A12 centre (23.85, 5.6141) radius 2 clockwise from (25.5821, 6.6141) to (25.85, 5.6141)
  arc A13 centre (27.85, 10.901) radius 4 clockwise from (23.85, 10.901) to (23.8809, 11.3971)
  arc A14 centre (18.35, 24.6826) radius 0.5 clockwise from (18.35, 25.1826) to (18.85, 24.6826)
  arc A15 centre (18.35, 24.65) radius 0.5 clockwise from (18.85, 24.65) to (18.35, 24.15)
  arc A16 centre (6.65, 23.65) radius 0.5 clockwise from (6.15, 23.65) to (6.65, 24.15)
  arc A17 centre (6.65, 25.6826) radius 0.5 clockwise from (6.65, 25.1826) to (6.15, 25.6826)
  point P6 (6, 96)
  point P13 (6, 96)
  point P14 (6, 19.15)
  point P10 (24, 96)
  point P15 (24, 96)
  point P16 (24, 19.15)
  point P17 (6.15, 19.15)
  point P49 (4.15, 6.15)
  point P48 (4.15, 17.15)
  point P56 (25.85, 17.15)
  point P57 (25.85, 6.15)
  point P66 (23.85, 11.15)
  point P19 (23.85, 99.15)
  point P71 (23.85, 99.15)
  point P12 (4.15, 19.15)
  point P11 (25.85, 4.15)
  point P65 (24.85, 19.15)
  point P58 (23.85, 10.15)
  horizontal L5
  vertical L29
  horizontal L15
  vertical L27
  perpendicular L5 L6
  perpendicular L1 L7
  coincident P6 P13
  coincident P14 L15
  perpendicular L8 L15
  coincident P10 P15
  coincident P16 L15
  perpendicular L9 L15
  coincident P17 L15
  perpendicular L10 L15
  perpendicular L7 L12
  perpendicular L7 L13
  tangent L13 A1
  tangent L6 A1
  tangent L13 A2
  tangent L7 A2
  equal A1 A2
  tangent L12 A3
  tangent L7 A3
  equal A1 A3
  tangent L12 A4
  tangent L6 A4
  equal A1 A4
  collinear L15 L16
  tangent A3 L22
  tangent A4 L23
  concentric A4 A5
  concentric A3 A6
  tangent A5 L20
  tangent L20 A6
  tangent A1 L24
  tangent A2 L25
  concentric A2 A7
  concentric A1 A8
  tangent A7 L21
  tangent L21 A8
  coincident P49 L27
  coincident P48 L26
  coincident P48 L27
  tangent L26 A9
  tangent L27 A9
  tangent L26 A10
  equal A9 A10
  coincident P56 L29
  tangent L28 A11
  coincident P57 L28
  coincident P57 L29
  tangent L28 A12
  tangent L29 A12
  tangent A10 L30
  vertical L31
  tangent A11 L31
  coincident P66 L31
  coincident P66 L32
  tangent L31 A13
  tangent L32 A13
  collinear L10 L31
  parallel L3 L33
  coincident P19 P71
  perpendicular L34 L35
  tangent L35 A14
  tangent L36 A14
  tangent L34 A15
  tangent L35 A15
  equal A14 A15
  tangent L34 A16
  equal A14 A16
  perpendicular L36 L37
  tangent L36 A17
  tangent L37 A17
  perpendicular L33 L38
  dimension "d54_1" distance L1 L5 = 0.15
  dimension "d56_1" distance L6 L7 = 5.7
  dimension "d57_1" distance L6 L27 = 8
  dimension "d58_1" distance L7 L29 = 8
  dimension "d61_1" distance L9 L10 = 0.15
  dimension "d91_1" distance L12 L13 = 12
  dimension "d92_1" distance L5 L12 = 1.5
  dimension "d93_1" distance L13 L15 = 1.5
  dimension "d94_1" radius A1 = 1
  dimension "d119_1" distance L14 L29 = 0.15
  dimension "d139_1" distance L18 L27 = 0.15
  dimension "d313_1" distance P12 P48 = 2
  dimension "d316_1" angle L26 L27 = 30
  dimension "d318_1" radius A9 = 2
  dimension "d319_1" distance P11 P57 = 2
  dimension "d322_1" angle L28 L29 = 30
  dimension "d370_1" distance L27 L30 = 2
  dimension "d371_1" distance L5 L19 = 15
  dimension "d372_1" distance L10 P65 = 1
  dimension "d373_1" distance P58 P66 = 1
  dimension "d374_1" radius A13 = 4
  dimension "d375_1" radius A11 = 2
  dimension "d379" distance L10 L35 = 5
  dimension "d380" radius A14 = 0.5
  dimension "d381" radius A17 = 0.5
  dimension "d382" distance L27 L38 = 2
  dimension "d383" distance L19 L33 = 80
  dimension "d384" distance L19 L34 = 5
  dimension "d385" distance L34 L36 = 1.0326
extrude "Extrude1" new body sketch "Sketch1" profile of L5 L29 L16 L27 L6 L7 L12 L13 A1 A2 A3 A4 L19 L20 A5 A6 A7 L21 A8 L22 L23 L24 L25 L26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 blind 2 named "d161_1" from offset 2.2 named "d160_1"
extrude "Extrude3" add sketch "Sketch1" profile of L10 L19 L33 L34 L35 L36 A14 A15 A16 L37 A17 L38 blind 1 named "d241_1" from offset 2.2 named "d243_1"
extrude "Extrude2" add sketch "Sketch1" profile of L6 L7 L12 L13 A1 A2 A3 A4 blind 5.8 named "d164_1" from offset 2.2 named "d163_1"
extrude "Extrude4" add sketch "Sketch1" profile of L12 L13 A1 A2 A3 A4 L20 A5 A6 A7 L21 A8 L22 L23 L24 L25 blind 1 named "d305_1" from offset 7 named "d304_1"
position "Position2"
chamfer "Chamfer1" distance 1 named "d307_1" distance 0.5 named "d324_1"
extrude "Extrude5" cut sketch "Sketch1" profile of L5 L29 L16 L27 L6 L7 L19 L20 A5 A6 A7 L21 A8 L22 L23 L24 L25 blind 1 named "d309_1" from offset 4.2 named "d308_1"
sketch "Sketch3" plane through (23.85, 0, 0) normal (1, 0, 0) x axis (0, 1, 0)
  line L1 (99.15, 2.2) -> (19.15, 2.2)
  line L2 (99.15, 3.2) -> (99.15, 2.2)
  line L3 (19.15, 3.2) -> (99.15, 3.2)
  line L4 (19.15, 2.2) -> (19.15, 3.2)
  line L5 (19.15, 4.2) -> (19.15, 2.2)
  line L6 (99.15, 4.2) -> (19.15, 4.2)
  line L7 (99.15, 2.2) -> (99.15, 4.2)
  point P2 (19.15, 2.2)
  point P6 (19.15, 2.2)
  point P3 (99.15, 2.2)
  point P9 (99.15, 2.2)
  point P7 (19.15, 4.2)
  coincident P2 P6
  perpendicular L3 L5
  perpendicular L5 L6
  coincident P3 P9
  vertical L7
  dimension "d386" distance P6 P7 = 2
loft "Loft3" sketch "Sketch3"
fillet "Fillet2" radius 2
extrude "Extrude6" cut sketch "Sketch1" profile of L34 L35 L36 A14 A15 A16 A17 L38 along normal blind 5
rectangular_pattern "R-Pattern1" countU 34 uSpaceDistance -71.5 vSpaceDistance 0
sketch "Sketch1" plane through (0, 0, 0) normal (0, 0, 1) x axis (1, 0, 0)
  line L1 (28, 2) -> (2, 2)
  line L2 (6, 96) -> (6, 100)
  line L3 (30, 0) -> (0, 0)
  line L4 (30, 100) -> (30, 0)
  line L5 (2, 98) -> (2, 2)
  line L6 (24, 96) -> (24, 100)
  line L7 (0, 100) -> (30, 100)
  line L8 (0, 0) -> (0, 100)
  line L9 (28, 98) -> (2, 98)
  line L10 (28, 2) -> (28, 98)
  line L11 (26, 4) -> (4, 4)
  line L12 (0.8, 36.7425) -> (0.8, 21)
  line L13 (24, 96) -> (26, 96)
  line L14 (4, 96) -> (6, 96)
  line L15 (5.1055, 19.9338) -> (0.9152, 44.9179)
  line L16 (4, 37.9285) -> (3, 37.9285)
  line L17 (4, 17.8) -> (0.8, 21)
  line L18 (4, 85) -> (0, 85)
  line L19 (4, 65) -> (0, 65)
  line L20 (29.2, 80) -> (26, 83.2)
  line L21 (29.2, 63.2575) -> (29.2, 80)
  line L22 (26, 62.0715) -> (26, 4)
  line L23 (26, 96) -> (26, 83.2)
  line L24 (26, 62.0715) -> (27, 62.0715)
  line L25 (28.014, 62.0715) -> (29.2, 63.2575)
  line L26 (24.8945, 80.0662) -> (29.0848, 55.0821)
  line L27 (24.1055, 79.9338) -> (28.1635, 55.7387)
  line L28 (4, 37.9285) -> (4, 96)
  line L29 (4, 4) -> (4, 17.8)
  line L30 (24, 96) -> (6, 96)
  line L31 (28.6, 44) -> (26, 44)
  line L32 (28.6, 4) -> (28.6, 44)
  line L33 (26, 4) -> (28.6, 4)
  line L34 (2.4, 54) -> (2.4, 65)
  line L35 (2.4, 96) -> (2.4, 85)
  line L36 (4, 96) -> (2.4, 96)
  line L37 (4, 54) -> (2.4, 54)
  line L38 (1.4, 4) -> (1.4, 20.4)
  line L39 (4, 4) -> (1.4, 4)
  line L40 (28.6, 96) -> (26, 96)
  line L41 (28.6, 80.6) -> (28.6, 96)
  line L42 (3, 37.9285) -> (1.9516, 44.1792)
  line L43 (1.986, 37.9285) -> (0.8, 45)
  line L44 (0.8, 36.7425) -> (1.986, 37.9285)
  line L45 (27, 62.0715) -> (28.0484, 55.8208)
  line L46 (28.014, 62.0715) -> (29.2, 55)
  line L47 (3.2, 44.3886) -> (1.9516, 44.1792)
  line L48 (3.0346, 45.3748) -> (3.2, 44.3886)
  line L49 (0.8, 45) -> (3.0346, 45.3748)
  line L50 (3.0848, 44.4706) -> (1.8365, 44.2613)
  line L51 (2.9525, 45.2596) -> (3.0848, 44.4706)
  line L52 (0.9152, 44.9179) -> (2.9525, 45.2596)
  line L53 (5.8945, 20.0662) -> (1.8365, 44.2613)
  line L54 (26.8, 55.6114) -> (28.0484, 55.8208)
  line L55 (26.9654, 54.6252) -> (26.8, 55.6114)
  line L56 (26.9654, 54.6252) -> (29.2, 55)
  line L57 (26.9152, 55.5294) -> (28.1635, 55.7387)
  line L58 (27.0475, 54.7404) -> (26.9152, 55.5294)
  line L59 (29.0848, 55.0821) -> (27.0475, 54.7404)
  line L60 (6, 4) -> (6, 96)
  line L61 (24, 4) -> (24, 96)
  line L62 (14, 4) -> (14, 96)
  line L63 (16, 4) -> (16, 96)
  circle C1 centre (2, 50) radius 1
  circle C2 centre (28, 98) radius 1
  circle C3 centre (2, 98) radius 1
  circle C4 centre (2, 2) radius 1
  circle C5 centre (28, 50) radius 1
  circle C6 centre (28, 2) radius 1
  arc A1 centre (5.5, 20) radius 0.4 clockwise from (5.8945, 20.0662) to (5.1055, 19.9338)
  arc A2 centre (24.5, 80) radius 0.4 clockwise from (24.1055, 79.9338) to (24.8945, 80.0662)
  point P6 (0, 0)
  point P15 (0, 0)
  point P14 (6, 100)
  point P12 (6, 96)
  point P3 (24, 100)
  point P17 (2, 98)
  point P21 (2, 98)
  point P10 (28, 2)
  point P23 (28, 2)
  point P11 (2, 2)
  point P22 (2, 2)
  point P9 (2, 50)
  point P24 (28, 50)
  point P25 (2, 98)
  point P13 (28, 98)
  point P20 (28, 98)
  point P1 (0, 0)
  point P29 (5.8523, 15.481)
  point P35 (4, 17.8)
  point P36 (0, 85)
  point P37 (4, 85)
  point P38 (0, 65)
  point P39 (4, 65)
  point P40 (26, 83.2)
  point P51 (26, 44)
  point P54 (2.4, 65)
  point P56 (2.4, 85)
  point P58 (4, 54)
  point P59 (1.4, 20.4)
  point P62 (28.6, 80.6)
  point P32 (5.8945, 20.0662)
  point P34 (5.8945, 20.0662)
  point P64 (1.986, 37.9285)
  point P42 (29.2, 63.2575)
  point P67 (29.2, 63.2575)
  point P45 (28.014, 62.0715)
  point P48 (24.8945, 80.0662)
  point P50 (24.8945, 80.0662)
  point P80 (6, 96)
  point P81 (6, 4)
  point P82 (24, 96)
  point P83 (24, 4)
  point P84 (14, 96)
  point P85 (14, 4)
  point P86 (16, 96)
  point P87 (16, 4)
  point P7 (30, 0)
  point P4 (0, 100)
  point P33 (5.5, 20)
  point P26 (0.8, 21)
  point P41 (29.2, 80)
  point P49 (24.5, 80)
  point P55 (2.4, 54)
  point P27 (4, 37.9285)
  point P28 (3, 37.9285)
  point P43 (26, 62.0715)
  point P44 (27, 62.0715)
  point P63 (0.8, 45)
  point P69 (3.2, 44.3886)
  point P66 (29.2, 55)
  point P75 (26.8, 55.6114)
  horizontal L3
  vertical L4
  horizontal L7
  vertical L8
  coincident P6 P15
  perpendicular L7 L28
  perpendicular L11 L28
  perpendicular L7 L22
  horizontal L13
  coincident P14 L7
  coincident P12 L13
  perpendicular L2 L13
  coincident P3 L7
  perpendicular L6 L13
  coincident P17 P21
  perpendicular L1 L4
  perpendicular L5 L7
  perpendicular L4 L9
  perpendicular L3 L10
  coincident P10 P23
  coincident P11 P22
  midpoint P9 L5
  midpoint P24 L10
  coincident P17 P25
  coincident P13 P20
  coincident P1 P6
  collinear L13 L14
  coincident P29 L15
  tangent L15 A1
  coincident P35 L28
  coincident L8 P36
  coincident P37 L28
  perpendicular L18 L28
  coincident L8 P38
  coincident P39 L28
  perpendicular L19 L28
  coincident P40 L22
  parallel L10 L21
  collinear L22 L23
  horizontal L24
  tangent L27 A2
  collinear L28 L29
  coincident L22 P51
  perpendicular L10 L31
  perpendicular L31 L32
  perpendicular L32 L33
  coincident L19 P54
  perpendicular L19 L34
  coincident L18 P56
  perpendicular L18 L35
  perpendicular L28 L36
  coincident L28 P58
  perpendicular L28 L37
  coincident L17 P59
  vertical L38
  perpendicular L38 L39
  perpendicular L23 L40
  coincident L20 P62
  perpendicular L40 L41
  coincident P32 P34
  horizontal L16
  coincident L16 P64
  coincident P42 P67
  coincident L24 P45
  coincident P48 P50
  tangent L26 A2
  parallel L15 L43
  perpendicular L42 L47
  perpendicular L43 L49
  perpendicular L50 L51
  parallel L49 L52
  parallel L48 L51
  parallel L47 L50
  parallel L15 L53
  tangent A1 L53
  parallel L27 L45
  perpendicular L45 L54
  perpendicular L54 L55
  perpendicular L27 L57
  perpendicular L57 L58
  perpendicular L46 L56
  parallel L56 L59
  coincident L30 P80
  coincident L11 P81
  perpendicular L11 L60
  coincident L30 P82
  coincident L11 P83
  perpendicular L11 L61
  coincident L30 P84
  coincident L11 P85
  perpendicular L11 L62
  coincident L30 P86
  coincident L11 P87
  perpendicular L11 L63
  dimension "d33_1" distance P6 P7 = 30
  dimension "d34_1" distance P4 P6 = 100
  dimension "d35_1" distance L4 L22 = 4
  dimension "d36_1" distance L3 L11 = 4
  dimension "d37_1" distance L7 L13 = 4
  dimension "d38_1" distance L2 L8 = 6
  dimension "d39_1" distance L4 L6 = 6 (= "d7")
  dimension "d40_1" distance L2 L6 = 18
  dimension "d41_1" distance L8 L28 = 4
  dimension "d42_1" diameter C2 = 2
  dimension "d43_1" diameter C1 = 2
  dimension "d44_1" diameter C5 = 2
  dimension "d45_1" diameter C4 = 2
  dimension "d46_1" diameter C6 = 2
  dimension "d47_1" distance L1 L3 = 2
  dimension "d48_1" distance L5 L8 = 2
  dimension "d49_1" diameter C3 = 2
  dimension "d50_1" distance L7 L9 = 2
  dimension "d51_1" distance L4 L10 = 2
  dimension "d64_1" distance L8 L12 = 0.8
  dimension "d87_1" distance L3 P33 = 20
  dimension "d89_1" angle L12 L17 = 135
  dimension "d90_1" distance L3 P26 = 21
  dimension "d95_1" distance L18 L19 = 20
  dimension "d96_1" distance L7 L18 = 15
  dimension "d100_1" angle L20 L21 = 135
  dimension "d101_1" distance L4 L21 = 0.8
  dimension "d102_1" distance L7 P41 = 20
  dimension "d105_1" angle L21 L25 = 135
  dimension "d115_1" distance L26 L27 = 0.8
  dimension "d118_1" distance L7 P49 = 20
  dimension "d204_1" distance L22 L32 = 2.6
  dimension "d205_1" distance L4 L32 = 1.4
  dimension "d206_1" distance L31 L33 = 40
  dimension "d225_1" distance P54 P55 = 11
  dimension "d226_1" distance L28 L35 = 1.6
  dimension "d227_1" distance L28 L34 = 1.6
  dimension "d282_1" distance L29 L38 = 2.6
  dimension "d283_1" distance L23 L41 = 2.6
  dimension "d311_1" distance L8 P33 = 5.5
  dimension "d328_1" distance L15 P64 = 0.1
  dimension "d329_1" distance P27 P28 = 1
  dimension "d330_1" angle L12 L44 = 135
  dimension "d331_1" distance P43 P44 = 1
  dimension "d335_1" distance P44 L27 = 0.1
  dimension "d338_1" distance L8 P63 = 0.8
  dimension "d340_1" distance L3 P63 = 45
  dimension "d341_1" distance L28 P69 = 0.8
  dimension "d343_1" distance L49 L52 = 0.1
  dimension "d344_1" distance L48 L51 = 0.1
  dimension "d345_1" distance L47 L50 = 0.1
  dimension "d346_1" distance L50 L52 = 0.8
  dimension "d347_1" distance L42 L53 = 0.1
  dimension "d348_1" distance L15 L53 = 0.8
  dimension "d350_1" distance L4 P66 = 0.8
  dimension "d351_1" distance L7 P66 = 45
  dimension "d352_1" distance L22 P75 = 0.8
  dimension "d353_1" distance L56 L59 = 0.1
  dimension "d354_1" distance L55 L58 = 0.1
  dimension "d355_1" distance L54 L57 = 0.1
  dimension "d356_1" distance L57 L59 = 0.8
  dimension "d362_1" distance L28 L60 = 2
  dimension "d363_1" distance L22 L61 = 2
  dimension "d364_1" distance L61 L63 = 8
  dimension "d365_1" distance L60 L62 = 8
  dimension "d366_1" distance L62 L63 = 2
  dimension "d376_1" distance L4 P49 = 5.5
extrude "Extrude1" new body sketch "Sketch1" profile of L29 C1 L2 L14 C2 C3 C4 L6 L7 C5 L8 L23 C6 L11 L12 L16 L53 L15 A1 L17 L18 L19 L20 L21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 along normal blind 2 named "d153_1"
extrude "Extrude5" cut sketch "Sketch1" profile of L11 L27 A2 L30 L60 L61 L62 L63 blind -0.4 named "d368_1" from offset 2 named "d367_1"
extrude "Extrude4" add sketch "Sketch1" profile of L29 L23 L17 L20 L31 L32 L33 L38 L39 L40 L41 along normal blind 4.2 named "d171_1"
extrude "Extrude2" add sketch "Sketch1" profile of L29 C1 L2 L14 C2 L3 C3 L4 C4 L6 L7 C5 L8 L23 C6 L11 L12 L16 L17 L18 L19 L20 L21 L24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 along normal blind 6.2 named "d155_1"
fillet "Fillet2" radius 2 named "d217_1"
chamfer "Chamfer2" distance 1 named "d220_1" distance 0.5 named "d221_1"
chamfer "Chamfer3" distance 0.4 named "d377_1" distance 3 named "d378_1"
extrude "Extrude1" new body sketch "Sketch1" profile of L29 C1 L2 L14 C2 L3 C3 L4 C4 L6 L7 C5 L8 L23 C6 L11 L12 L16 L17 L18 L19 L20 L21 L24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 blind 6.2 named "d184_1" from offset 6.2 named "d183_1"
extrude "Extrude5" add sketch "Sketch1" profile of L29 L14 L8 L23 L11 L12 L16 L53 L15 A1 L17 L18 L19 L20 L21 L24 L25 L26 L27 A2 L30 L31 L32 L33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 blind 2 named "d212_1" from offset 10.4 named "d211_1"
extrude "Extrude3" add sketch "Sketch1" profile of C1 C2 C3 C4 C5 C6 blind 2 named "d193_1" from offset 10.4 named "d192_1"
extrude "Extrude4" add sketch "Sketch1" profile of L2 L6 L7 L30 blind 8 named "d196_1" from offset 4.4 named "d195_1"
fillet "Fillet2" radius 2 named "d215_1"
chamfer "Chamfer2" distance 1 named "d218_1" distance 0.5 named "d219_1"
canvas "Canvas1"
